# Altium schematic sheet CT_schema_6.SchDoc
size 578 x 363 mm
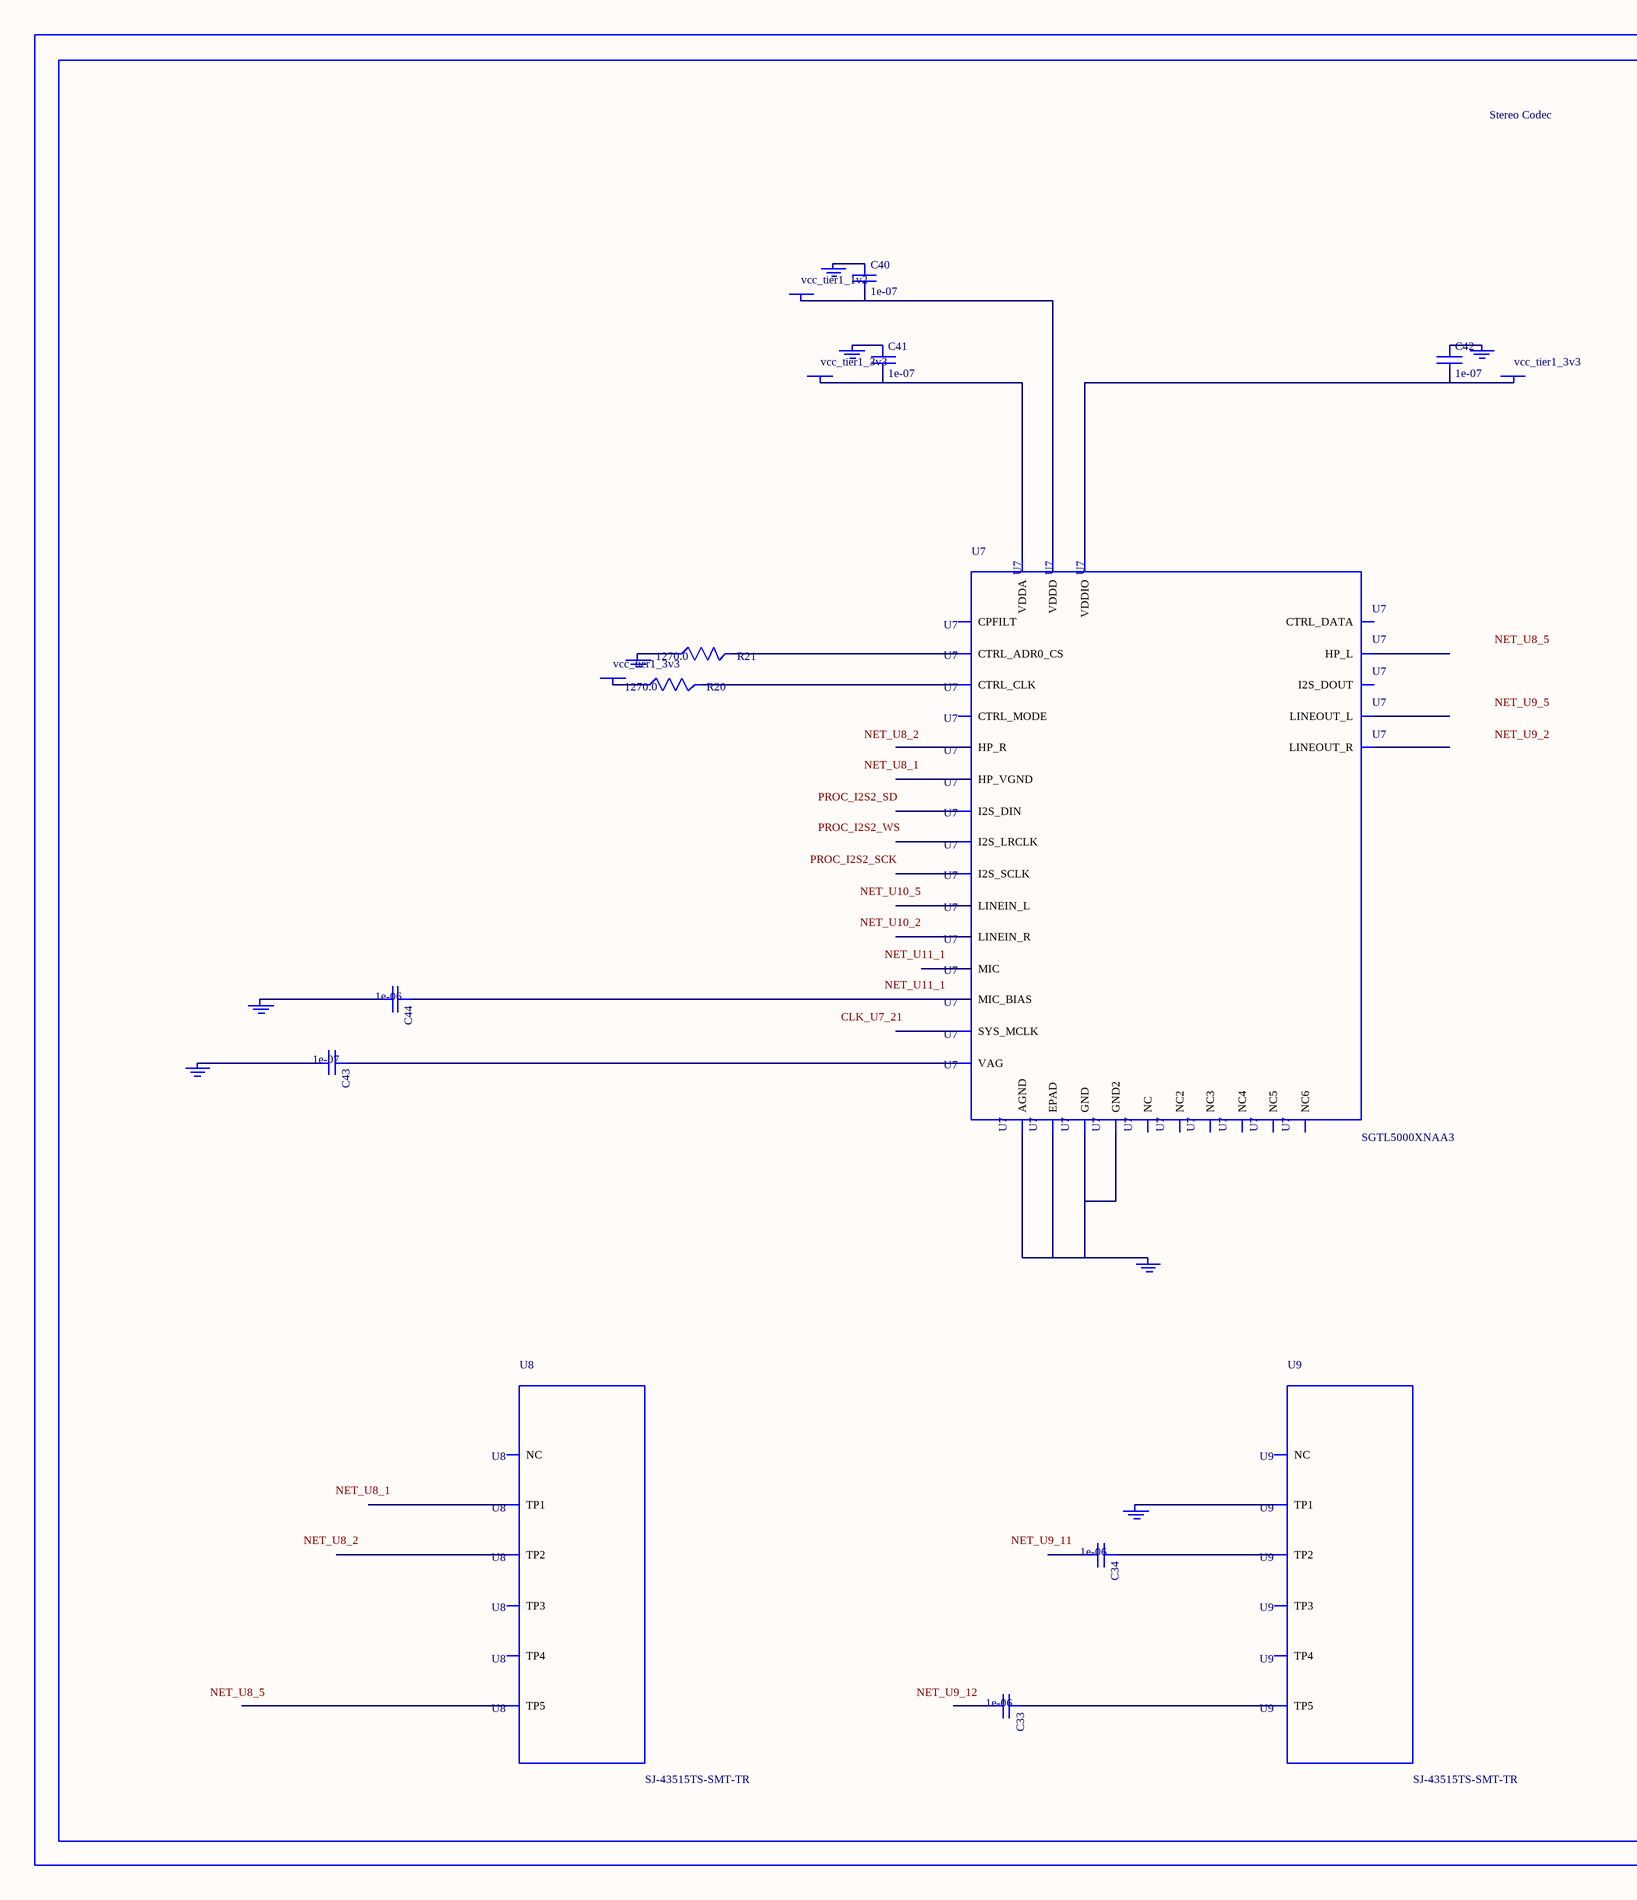
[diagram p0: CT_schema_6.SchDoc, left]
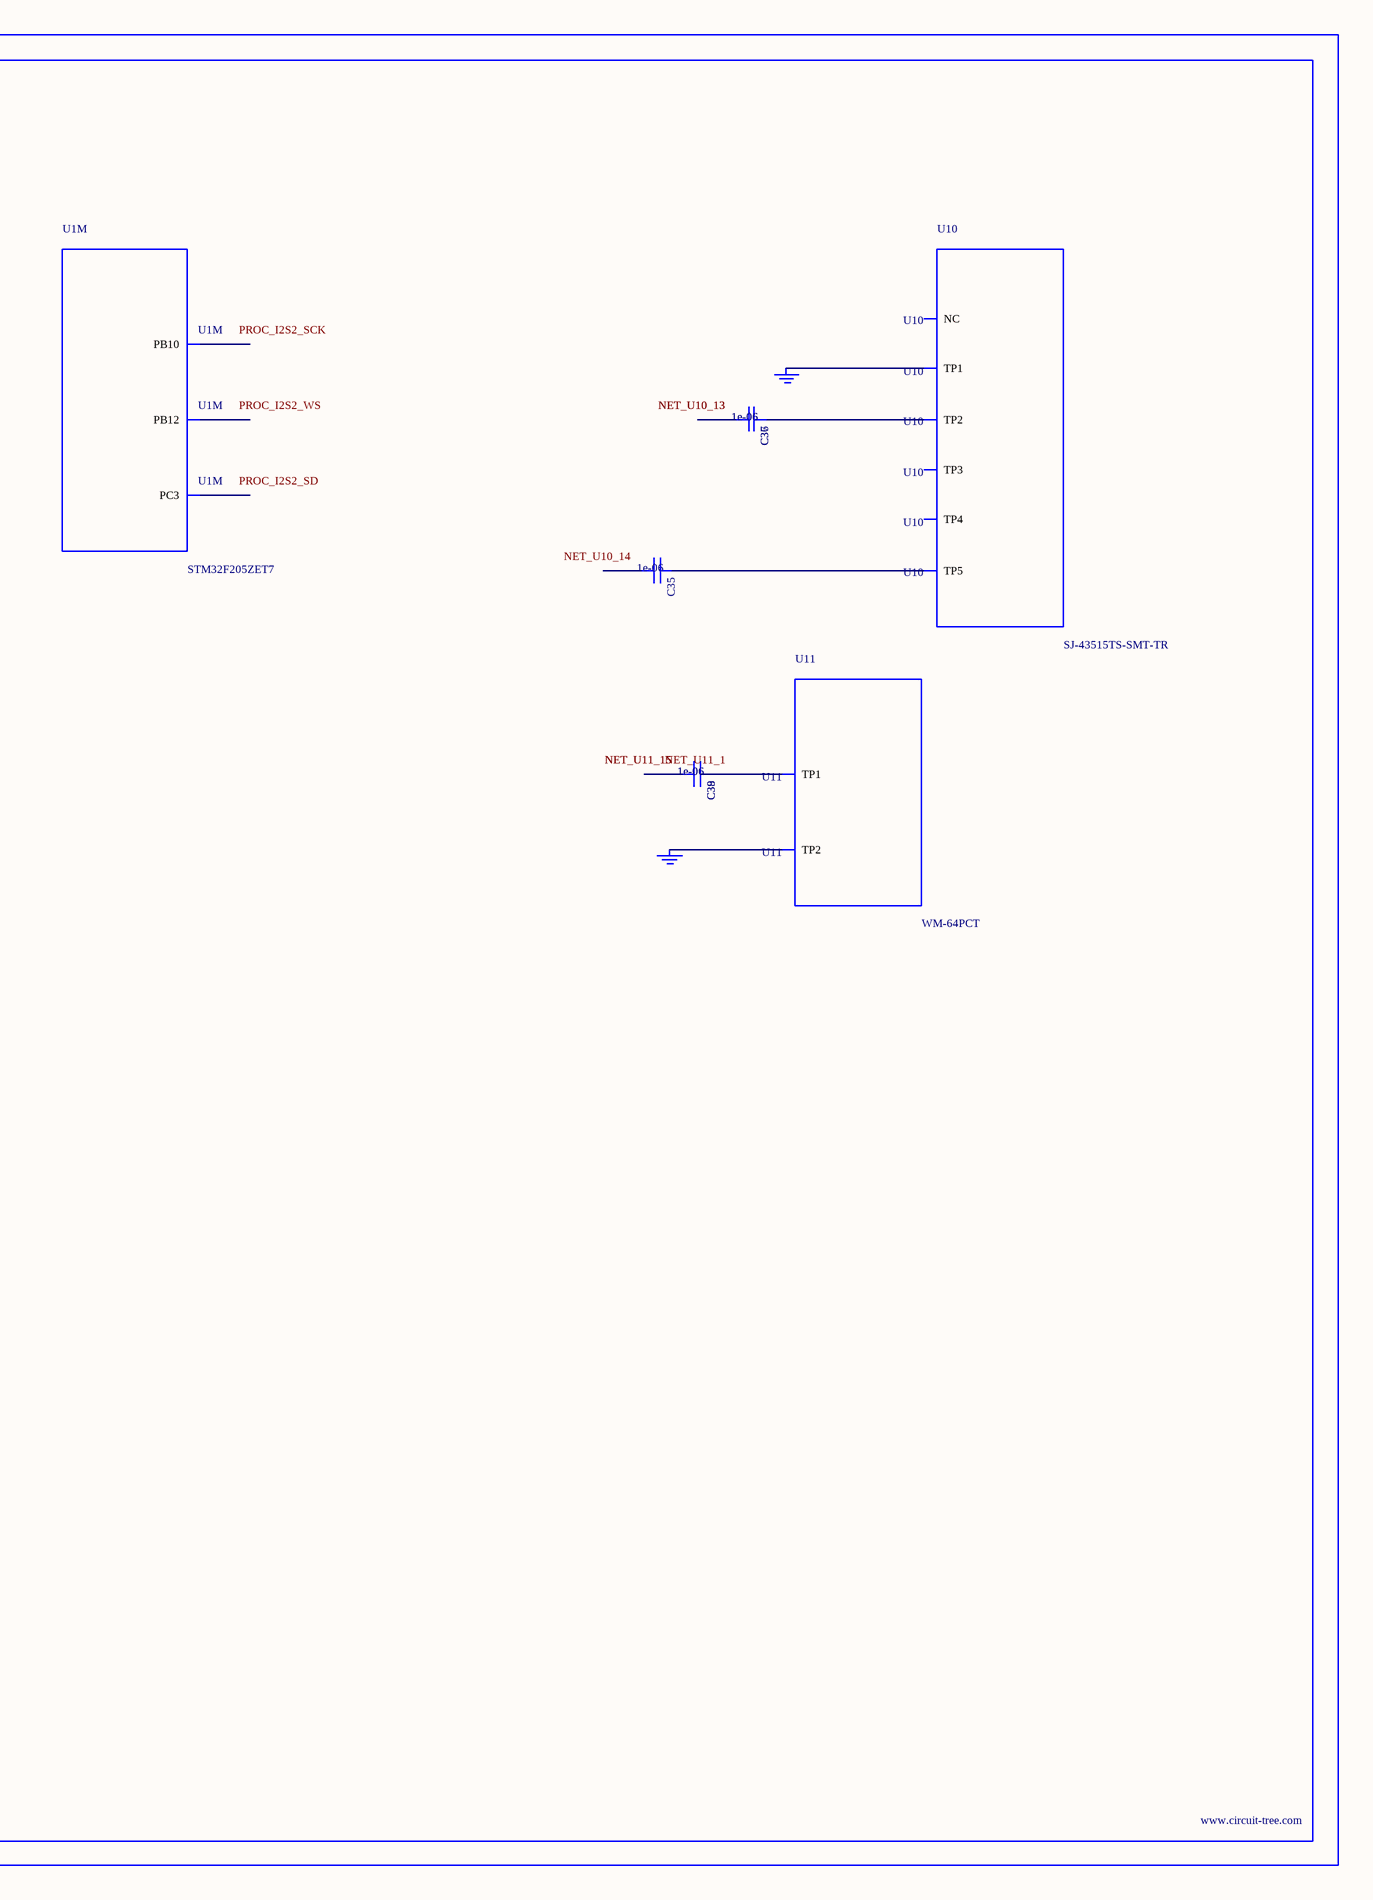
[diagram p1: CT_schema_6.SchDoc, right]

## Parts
BORDER5  (no value)
C33  1e-06  [C0603]
C34  1e-06  [C0603]
C35  1e-06  [C0603]
C36  1e-06  [C0603]
C37  1e-06  [C0603]
C38  1e-06  [C0603]
C39  1e-06  [C0603]
C40  1e-07  [C0402]
C41  1e-07  [C0402]
C42  1e-07  [C0402]
C43  1e-07  [C0402]
C44  1e-06  [C0603]
GND_INSTANCE_5_0  (no value)
GND_INSTANCE_5_1  (no value)
GND_INSTANCE_5_2  (no value)
GND_INSTANCE_5_3  (no value)
GND_INSTANCE_5_4  (no value)
GND_INSTANCE_5_5  (no value)
GND_INSTANCE_5_6  (no value)
GND_INSTANCE_5_7  (no value)
GND_INSTANCE_5_8  (no value)
GND_INSTANCE_5_9  (no value)
GND_INSTANCE_5_10  (no value)
POWER_INSTANCE_5_0  vcc_tier1_3v3
POWER_INSTANCE_5_1  vcc_tier1_3v3
POWER_INSTANCE_5_2  vcc_tier1_3v3
POWER_INSTANCE_5_3  vcc_tier1_1v2
R20  1270.0  [R0603]
R21  1270.0  [R0603]
U1  STM32F205ZET7  [LQFP144]  (part M of 13)
U7  SGTL5000XNAA3  [QFN-32]
U8  SJ-43515TS-SMT-TR  [SJ-43515TS-SMT-TR]
U9  SJ-43515TS-SMT-TR  [SJ-43515TS-SMT-TR]
U10  SJ-43515TS-SMT-TR  [SJ-43515TS-SMT-TR]
U11  WM-64PCT  [WM-64PC]

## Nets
NetC33_1: C33.1 U9.5(TP5)
NetC34_1: C34.1 U9.2(TP2)
NetC35_1: C35.1 U10.5(TP5)
NetC36_1: C36.1 C37.1 U10.2(TP2)
NetC36_2: C36.2 C37.2
NetC38_1: C38.1 C39.1 U11.1(TP1)
NetC38_2: C38.2 C39.2
NetC40_1: C40.1 GND_INSTANCE_5_5.0(GND)
NetC40_2: C40.2 POWER_INSTANCE_5_3.0(PWR) U7.30(VDDD)
NetC41_1: C41.1 GND_INSTANCE_5_1.0(GND)
NetC41_2: C41.2 POWER_INSTANCE_5_0.0(PWR) U7.5(VDDA)
NetC42_1: C42.1 GND_INSTANCE_5_4.0(GND)
NetC42_2: C42.2 POWER_INSTANCE_5_1.0(PWR) U7.20(VDDIO)
NetC43_1: C43.1 U7.10(VAG)
NetC43_2: C43.2 GND_INSTANCE_5_2.0(GND)
NetC44_1: C44.1 U7.16(MIC_BIAS)
NetC44_2: C44.2 GND_INSTANCE_5_3.0(GND)
NetGND_INSTANCE_5_0_0: GND_INSTANCE_5_0.0(GND) U7.1(GND) U7.3(GND2) U7.7(AGND) U7.EXP(EPAD)
NetGND_INSTANCE_5_6_0: GND_INSTANCE_5_6.0(GND) R21.1
NetGND_INSTANCE_5_7_0: GND_INSTANCE_5_7.0(GND) U9.1(TP1)
NetGND_INSTANCE_5_8_0: GND_INSTANCE_5_8.0(GND) GND_INSTANCE_5_9.0(GND) U10.1(TP1)
NetGND_INSTANCE_5_10_0: GND_INSTANCE_5_10.0(GND) U11.2(TP2)
NetPOWER_INSTANCE_5_2_0: POWER_INSTANCE_5_2.0(PWR) R20.1
NetR20_2: R20.2 U7.29(CTRL_CLK)
NetR21_2: R21.2 U7.31(CTRL_ADR0_CS)

Not connected (* = marked no-connect by the designer): C33 2; C34 2; C35 2; U1 29(PC3) 69(PB10) 73(PB12); U7 2(HP_R) 4(HP_VGND) 6(HP_L) 8(NC) 9(NC2) 11(LINEOUT_R) 12(LINEOUT_L) 13(LINEIN_R) 14(LINEIN_L) 15(MIC) 17(NC3) 18(CPFILT) 19(NC4) 21(SYS_MCLK) 22(NC5) 23(I2S_LRCLK) 24(I2S_SCLK) 25(I2S_DOUT) 26(I2S_DIN) 27(CTRL_DATA) 28(NC6) 32(CTRL_MODE); U8 1(TP1) 2(TP2) 3(TP3) 4(TP4) 5(TP5) 6(NC); U9 3(TP3) 4(TP4) 6(NC); U10 3(TP3) 4(TP4) 6(NC)

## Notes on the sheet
- Labels drawn without touching a wire or pin: CLK_U7_21, NET_U8_1, NET_U8_2, NET_U8_5, NET_U9_2, NET_U9_5, NET_U9_11, NET_U9_12, NET_U10_2, NET_U10_5, NET_U10_14, NET_U11_1, PROC_I2S2_SCK, PROC_I2S2_SD, PROC_I2S2_WS

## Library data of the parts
BORDER5 = BORDER_PAGE5
C33-C39 C44 = C0603C105K3RACTU
C40-C43 = C0402C104K3RACTU
GND_INSTANCE_5_0-GND_INSTANCE_5_10 = GND
POWER_INSTANCE_5_0-POWER_INSTANCE_5_3 = PWR
R20 R21 = RC0603FR-071K27L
